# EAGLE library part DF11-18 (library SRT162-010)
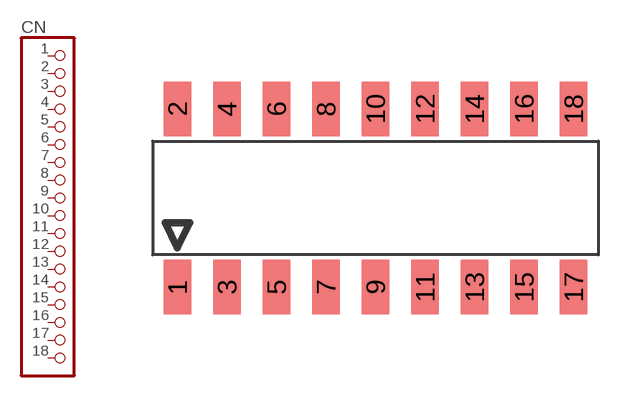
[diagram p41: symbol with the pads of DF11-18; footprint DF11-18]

Designator prefix CN

## DF11-18  [DF11-18]
1  1  pas
2  2  pas
3  3  pas
4  4  pas
5  5  pas
6  6  pas
7  7  pas
8  8  pas
9  9  pas
10  10  pas
11  11  pas
12  12  pas
13  13  pas
14  14  pas
15  15  pas
16  16  pas
17  17  pas
18  18  pas

## Footprint DF11-18 (pad centres in mm)
smd 1.1 x 2.2: 1 -8,-3.6; 2 -8,3.6; 3 -6,-3.6; 4 -6,3.6; 5 -4,-3.6; 6 -4,3.6; 7 -2,-3.6; 8 -2,3.6; 9 0,-3.6; 10 0,3.6; 11 2,-3.6; 12 2,3.6; 13 4,-3.6; 14 4,3.6; 15 6,-3.6; 16 6,3.6; 17 8,-3.6; 18 8,3.6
